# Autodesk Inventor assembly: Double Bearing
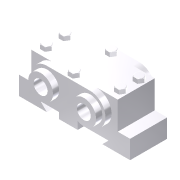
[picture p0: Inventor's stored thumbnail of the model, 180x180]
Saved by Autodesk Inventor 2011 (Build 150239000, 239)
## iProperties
Shininess: 64.0
Length Units: 11269
Angle Units: 11279
Time Units: 11290
Mass Units: 11283
Length Display Precision: 3
Angle Display Precision: 2
Created: 2002-02
Part Number: Double Bearing
Document SubType Name: Assembly
Designer: ***
Density: 0.0
Volumn: 0.0
Area: 0.0
PropertySet Name: Model Information
Control State: 0
Master: False
Checked Out: False
Author: ***
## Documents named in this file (5)
- C:\Users\CADSoft\Desktop\part files\c12-inv-2011-prt\c12-tut02-inv\Double Bearing.iam
- C:\Inventor_2011\tutorials\c12\Double Bearing\Base.ipt
- C:\Inventor_2011\tutorials\c12\Double Bearing\Cap.ipt
- C:\Inventor_2011\tutorials\c12\Double Bearing\Bushing.ipt
- C:\Inventor_2011\tutorials\c12\Double Bearing\Bolt.ipt
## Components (10 placed, 4 different names)
1. Base:1 — Insert:1, Insert:2
2. Cap:1 — Insert:1, Insert:2, Insert:3, Insert:4, Insert:5, Insert:6
3. Bushing:1 — Insert:3
4. Bushing:2 — Insert:4
5. Bolt:1 — Insert:5
6. Bolt:6
7. Bolt:7
8. Bolt:8
9. Bolt:5 — Insert:6
10. Bolt:9
## Component patterns: Component Pattern 1 (4 elements), Component Pattern 2 (2 elements)
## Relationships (6: Insert 6)
- Insert:1: Base:1 ↔ Cap:1
- Insert:2: Base:1 ↔ Cap:1
- Insert:3: Cap:1 ↔ Bushing:1
- Insert:4: Cap:1 ↔ Bushing:2
- Insert:5: Cap:1 ↔ Bolt:1
- Insert:6: Cap:1 ↔ Bolt:5
